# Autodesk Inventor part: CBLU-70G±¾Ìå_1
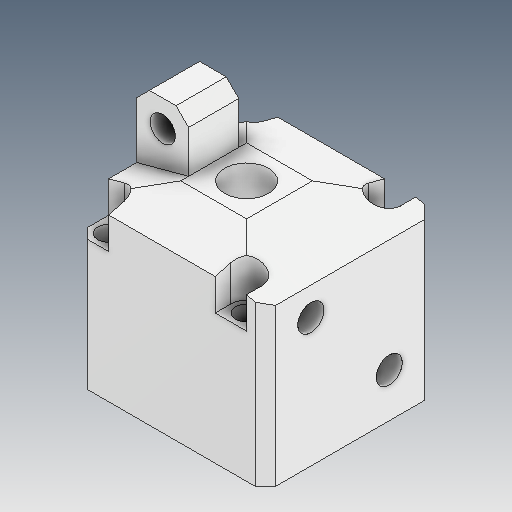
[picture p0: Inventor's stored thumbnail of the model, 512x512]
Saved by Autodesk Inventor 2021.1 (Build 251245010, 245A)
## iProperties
Created: 2021-05
Part Number: CBLU-70G±¾Ìå_1
Material: Ogólny
Document SubType Name: Modeling
Designer: user
Density: 1 g/cm^3
Appearance: Domyślna
Author: user
Revision Number: ÈÎºÎ
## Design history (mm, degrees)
feature "ÊäÈë1"
feature "ÊäÈë2"
node "Bryła1"
node "Bryła2"
